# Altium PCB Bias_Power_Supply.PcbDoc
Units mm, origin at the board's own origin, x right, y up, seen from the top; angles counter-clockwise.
Board outline 100 x 60 mm, 4 copper layers (Top Layer, Layer 1, Layer 2, Bottom Layer), stack 0.603 mm thick; 70 components, 35 nets, 168 pads, 109 vias.
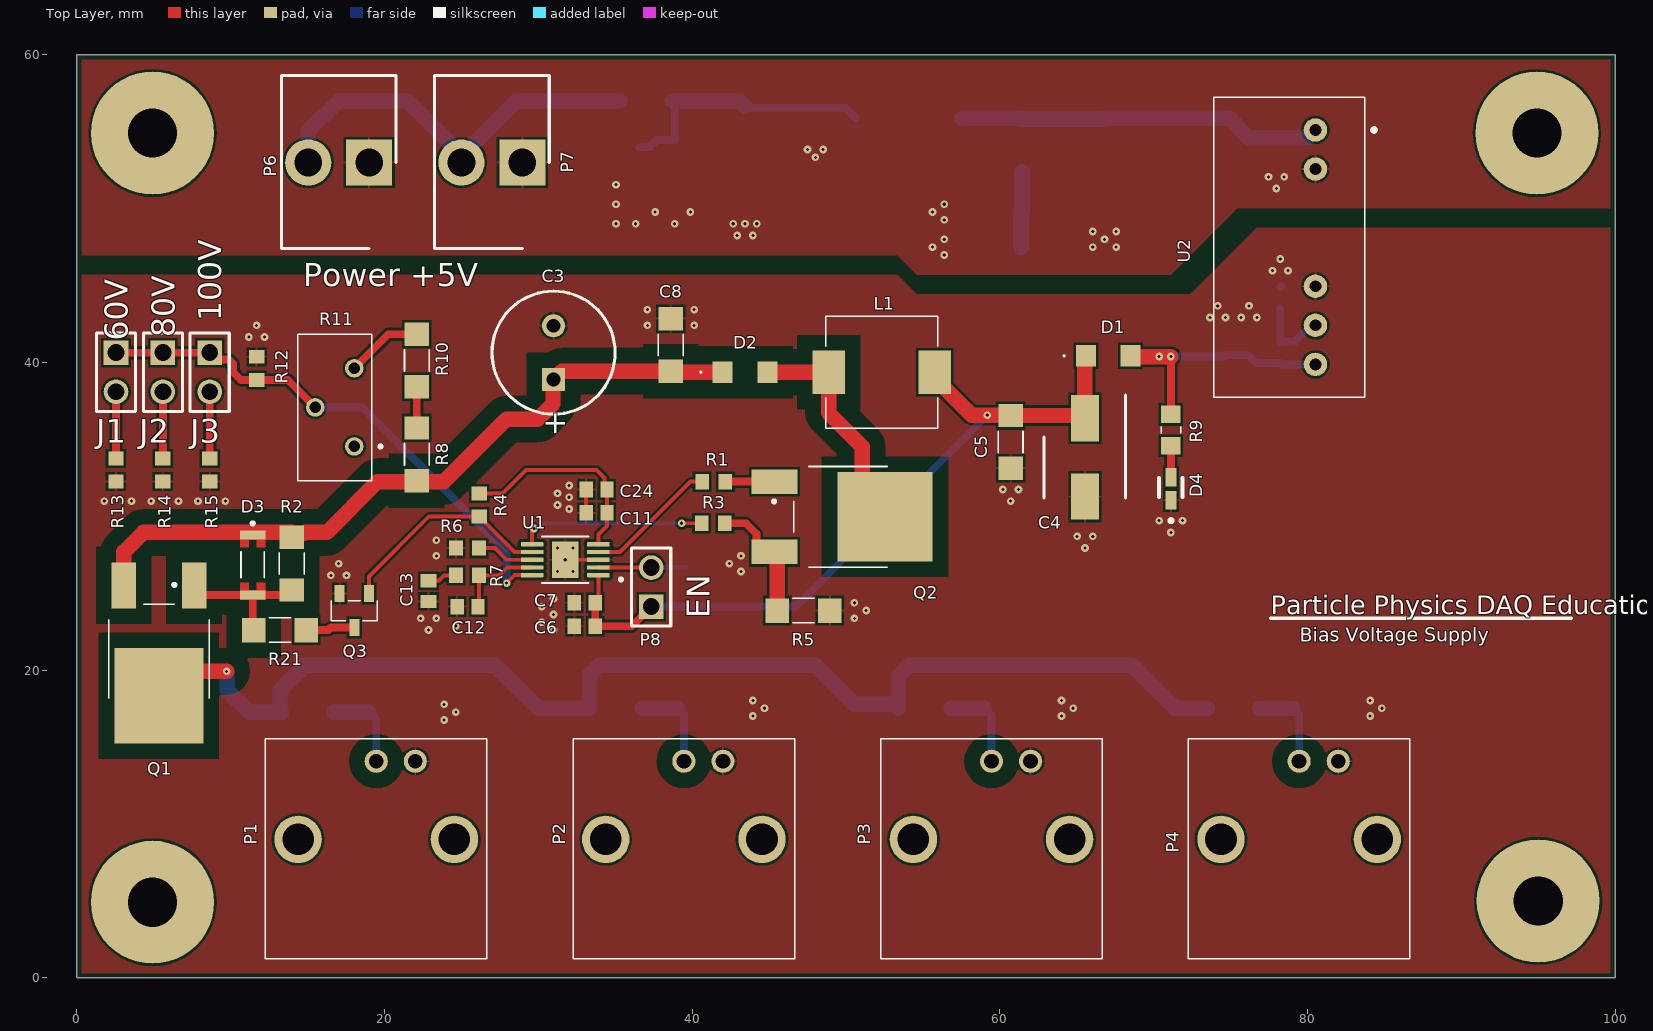
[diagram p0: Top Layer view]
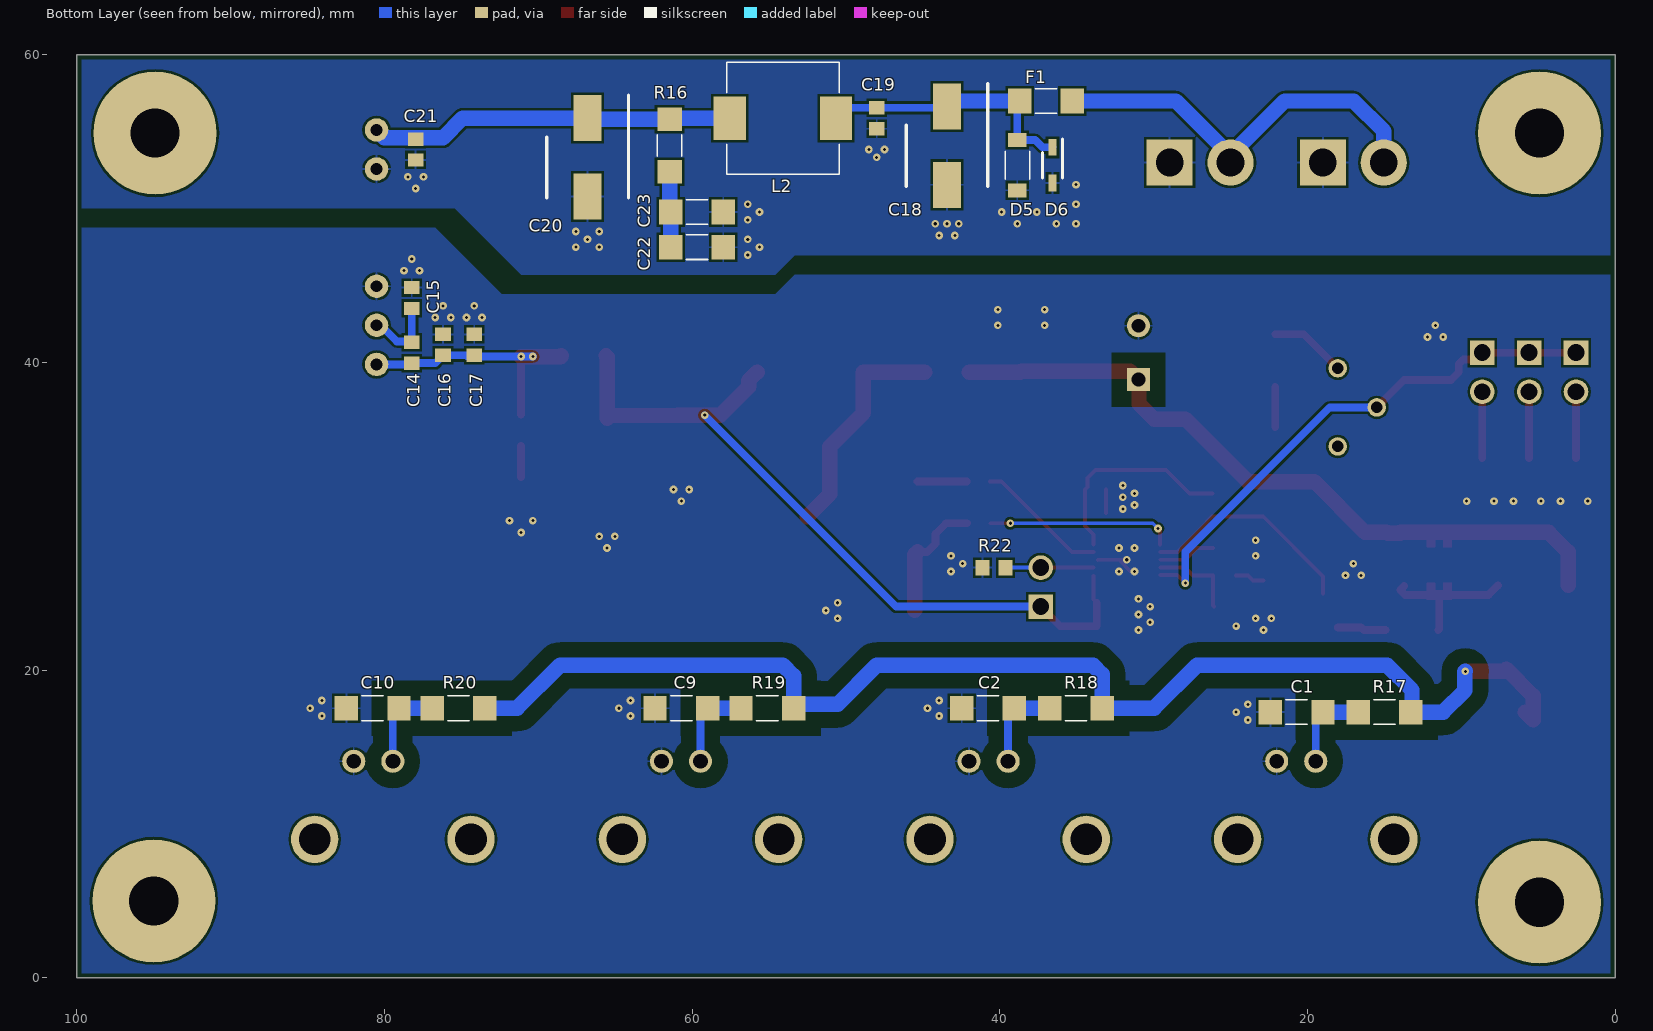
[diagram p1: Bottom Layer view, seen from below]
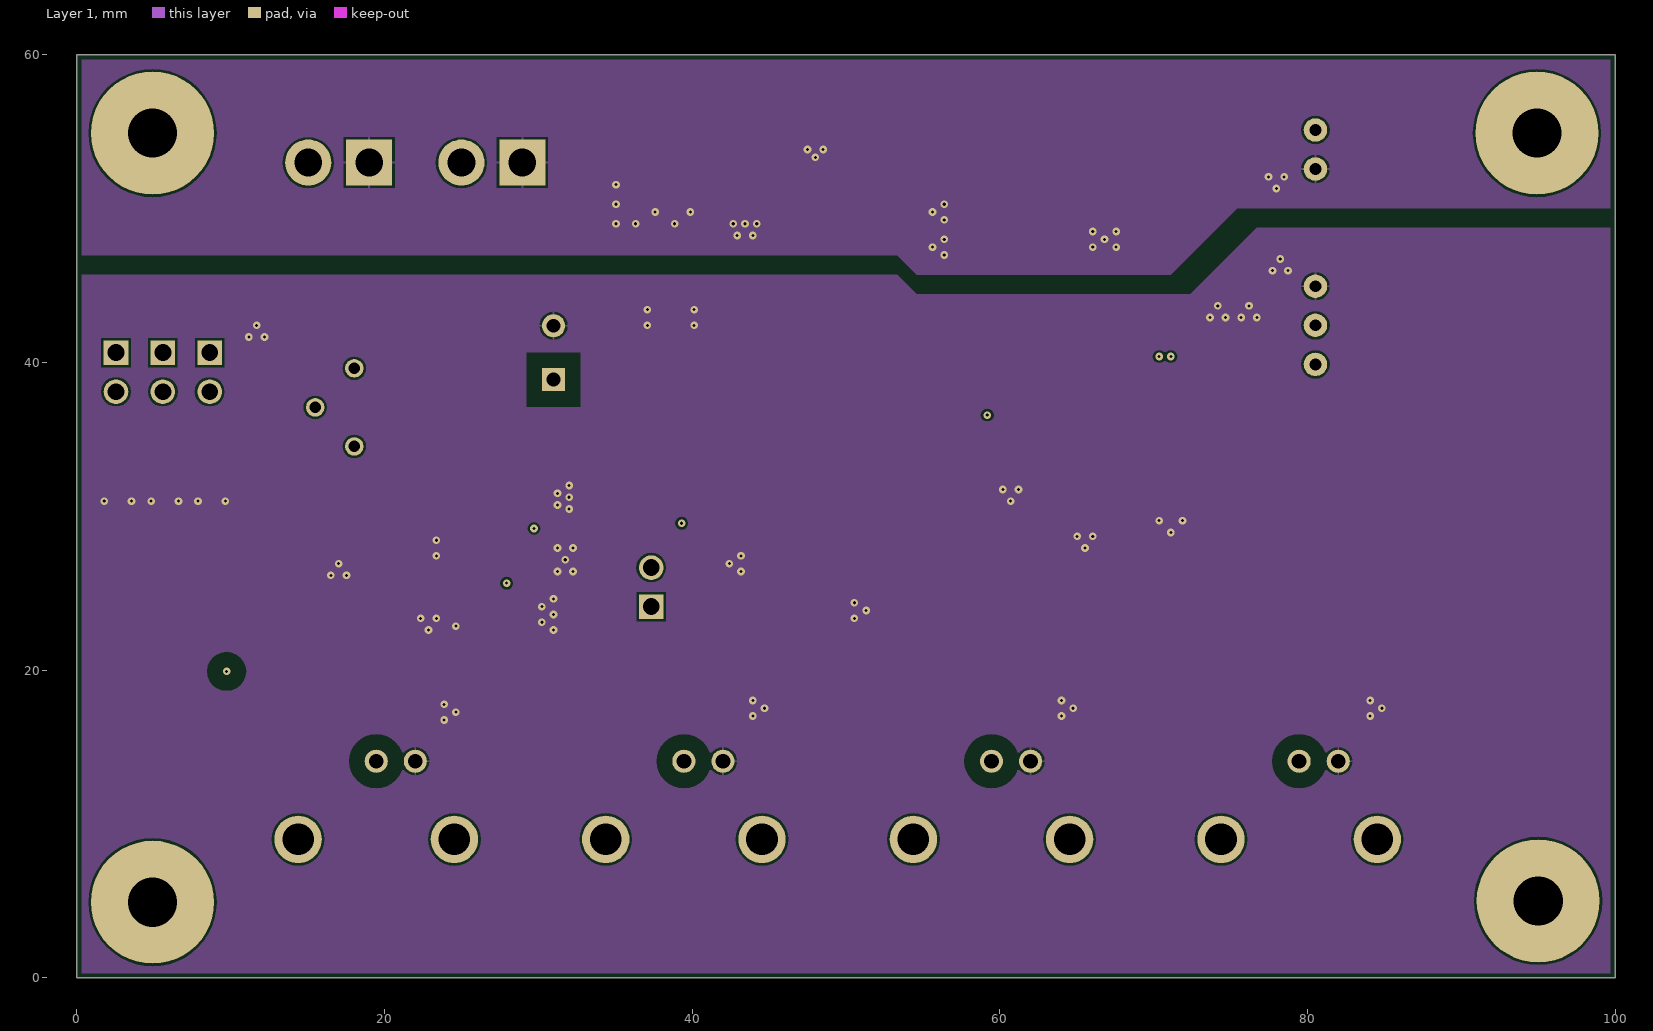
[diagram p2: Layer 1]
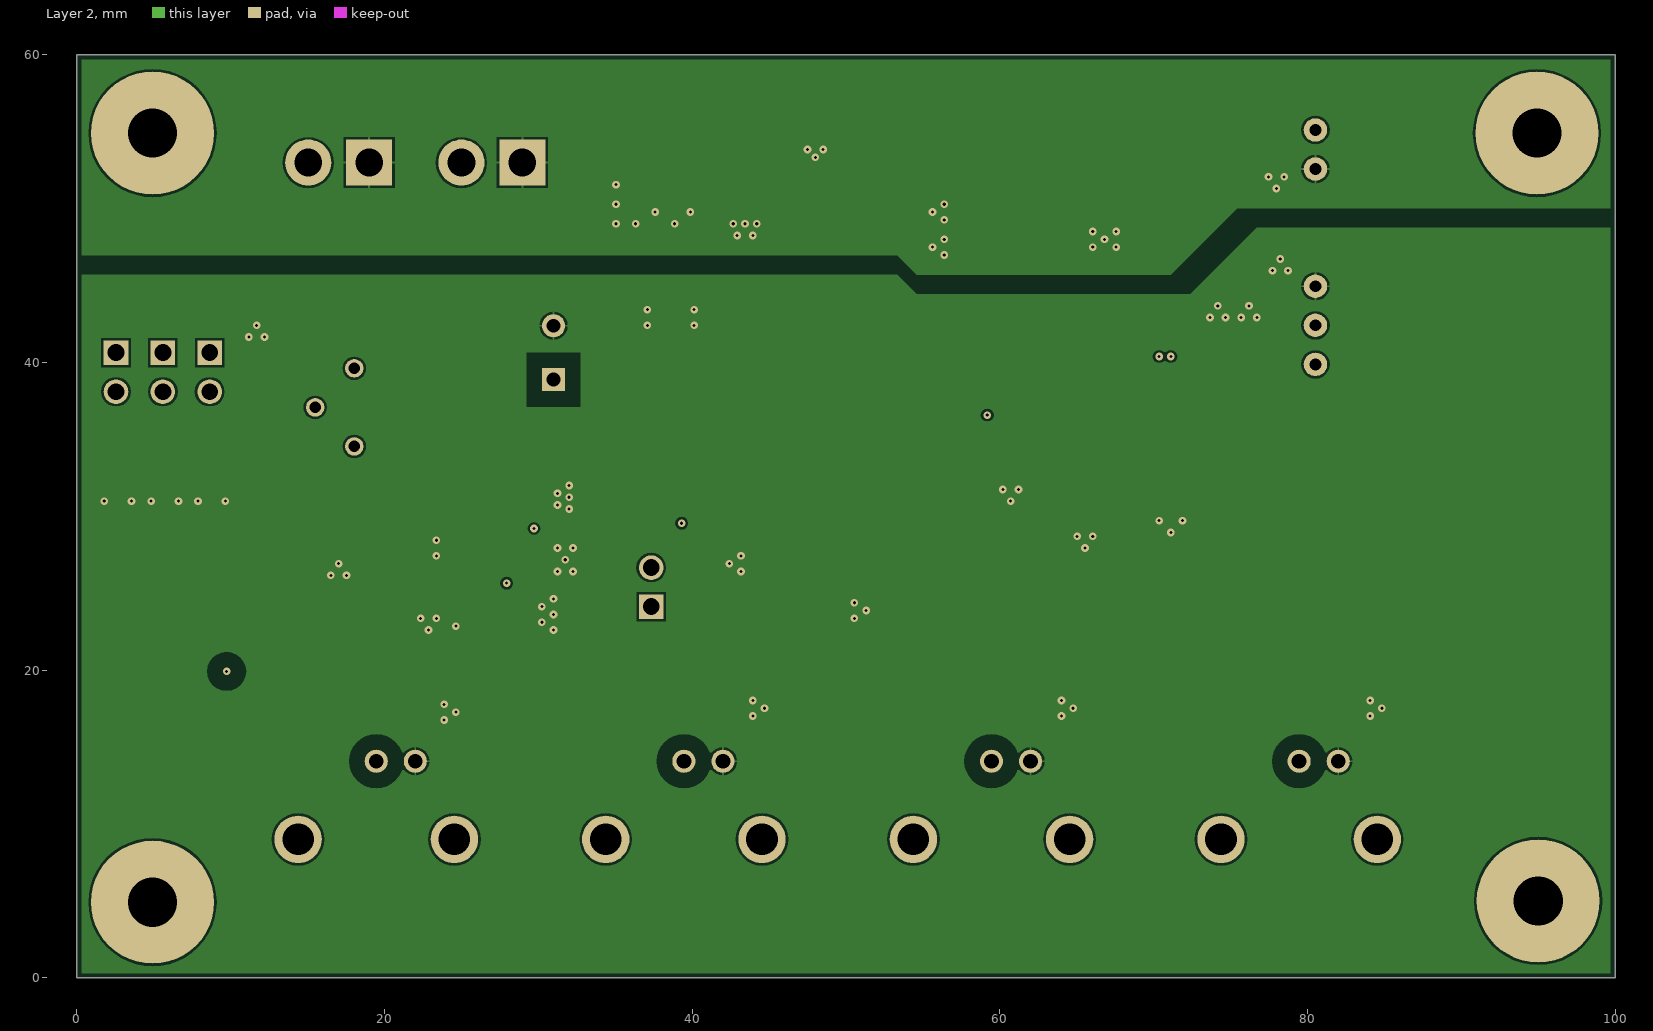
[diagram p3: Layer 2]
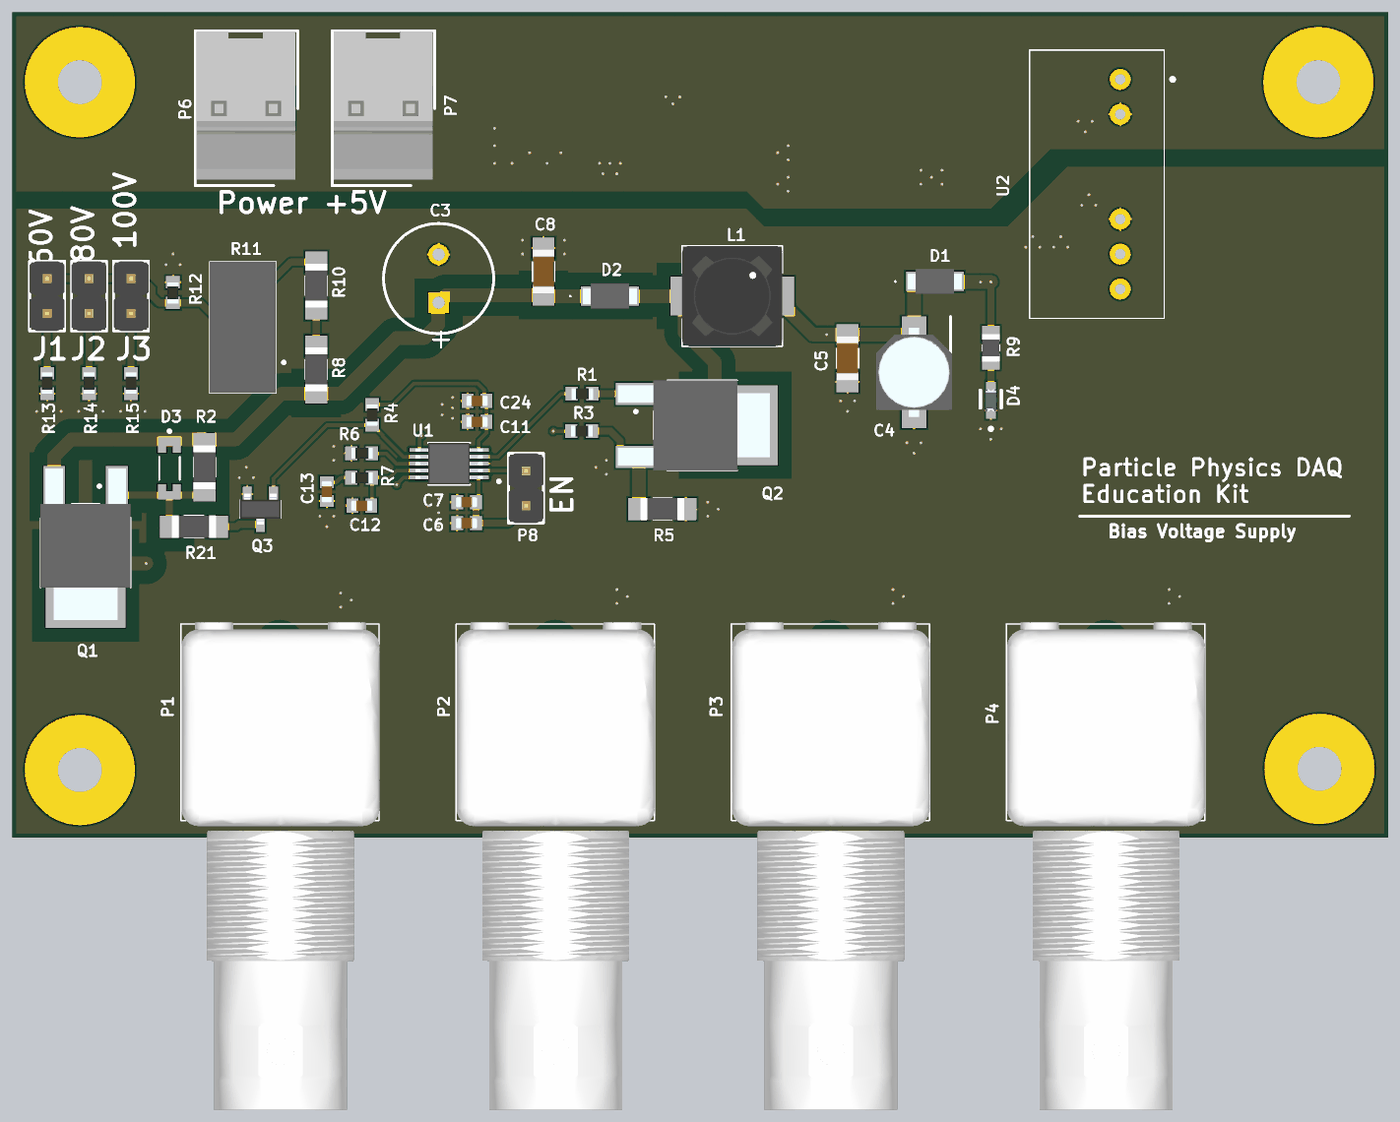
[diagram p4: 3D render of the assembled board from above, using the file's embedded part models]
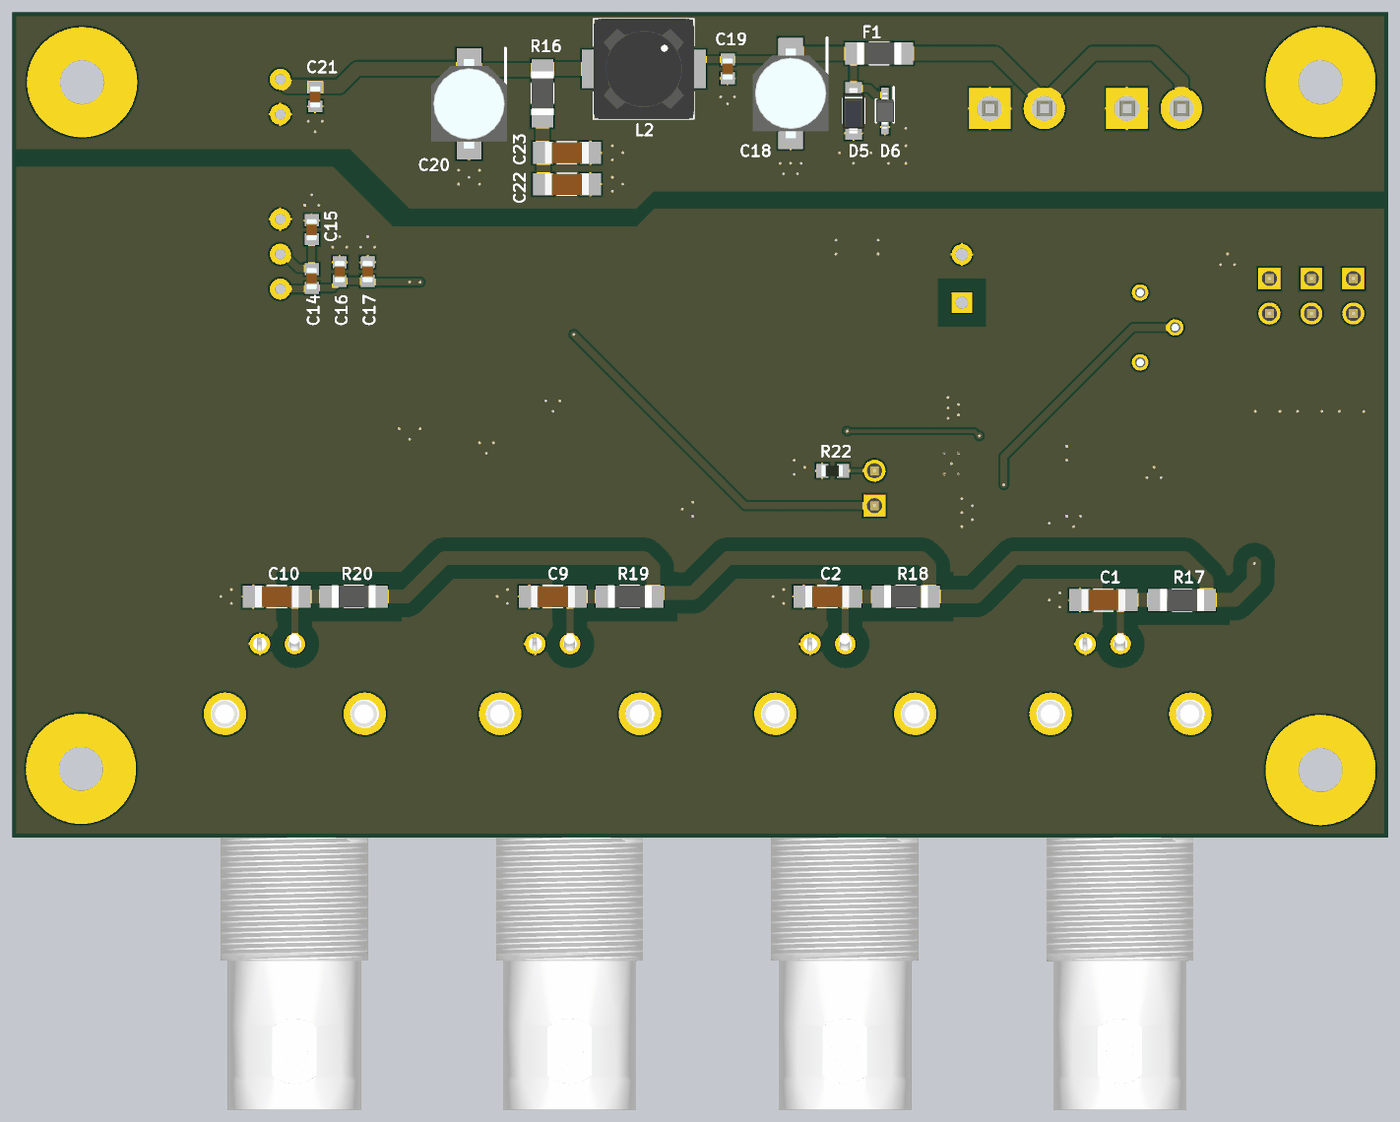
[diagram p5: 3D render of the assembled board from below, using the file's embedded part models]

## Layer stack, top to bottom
Top Solder: solder mask 0.0102, Solder Resist, Dk 3.5
Top Layer: signal copper 0.0356
Dielectric 2: prepreg 0.0711, PP-006, Dk 4.1
Layer 1: signal copper 0.035
Dielectric 1: core 0.32, FR-4, Dk 4.8
Layer 2: signal copper 0.035
Dielectric 3: prepreg 0.0711, PP-006, Dk 4.1
Bottom Layer: signal copper 0.0356
Bottom Solder: solder mask 0.0102, Solder Resist, Dk 3.5

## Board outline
0,0 0,60 100,60 100,0

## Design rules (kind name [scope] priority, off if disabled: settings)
AcuteAngle [All] p1: minimum=6.00000000000000E+0001 checktracksonly=FALSE
BoardOutlineClearance [All] p1: gap=0.3 ignorepadtopadclearanceinfootprint=FALSE
Clearance "Clearance - Controller" [HasFootprint('SOP50P490X110-11N')] p1: gap=0.2 ignorepadtopadclearanceinfootprint=FALSE
Clearance Clearance_HV [InNetClass('HV')] p2: gap=1 ignorepadtopadclearanceinfootprint=FALSE
Clearance "Clearance main" [All] p3: gap=0.15 ignorepadtopadclearanceinfootprint=FALSE
HoleSize [All] p1: absolutevalues=TRUE maxlimit=5 minlimit=0.2 maxpercent=80.000 minpercent=20.000
MinimumSolderMaskSliver [All] p1: minsoldermaskwidth=0.08
PolygonConnect [All] p1: thpad.connectstyle=Relief thpad.reliefconductorwidth=0.15 thpad.reliefentries=4 thpad.polygonreliefangle="90 Angle" thpad.airgapwidth=0.15 smdpad.connectstyle=Relief smdpad.reliefconductorwidth=0.15 smdpad.reliefentries=4 smdpad.polygonreliefangle="90 Angle" smdpad.airgapwidth=0.15 via.connectstyle=Direct via.reliefconductorwidth=0.254 via.reliefentries=4 via.polygonreliefangle="90 Angle" via.airgapwidth=0.254
RoutingVias [All] p1: holewidth=0.7 width=1.27 viastyle="Through Hole" minholewidth=0.7 minwidth=1.27 maxholewidth=0.7 maxwidth=1.27
SilkToSilkClearance [All] p1: silktosilkclearance=0.1
SilkToSolderMaskClearance [IsPad] p1: minsilkscreentomaskgap=0.1 clearancetoexposedcopper=TRUE
SolderMaskExpansion [All] p1: expansion=0.07
Width [All] p1: maxlimit=1.016 minlimit=0.254 preferedwidth=0.508
26 further rules are at their usual default settings.

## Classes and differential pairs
net class HV: HV_out NetC1_2 NetC2_2 NetC3_1 NetC9_2 NetC10_2 NetD2_1 NetD3_1

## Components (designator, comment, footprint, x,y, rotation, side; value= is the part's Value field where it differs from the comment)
C1 "100n" SMD_CAPACITOR_1206 20.701,17.272 r180 bottom
C2 "100n" SMD_CAPACITOR_1206 40.767,17.526 r180 bottom
C3 "10u" CAPPR3.5-8x11.5 30.988,40.64 r90 top
C4 "10u" SMD_CAP_POL_D5.0mm 65.532,33.83 r270 top
C5 "10u" SMD_CAPACITOR_1206 60.706,34.846 r90 top
C6 "1u" SMD_CAPACITOR_0603 33.02,22.86 r0 top
C7 "100n" SMD_CAPACITOR_0603 33.02,24.384 r0 top
C8 "100n" SMD_CAPACITOR_1206 38.608,41.148 r270 top
C9 "100n" SMD_CAPACITOR_1206 60.706,17.526 r180 bottom
C10 "100n" SMD_CAPACITOR_1206 80.772,17.526 r180 bottom
C11 "100n" SMD_CAPACITOR_0603 33.782,30.226 r0 top
C12 "D.N.P." SMD_CAPACITOR_0603 25.4,24.13 r0 top
C13 "1n" SMD_CAPACITOR_0603 22.86,25.146 r90 top
C14 "100n" SMD_CAPACITOR_0603 78.232,40.64 r270 bottom
C15 "100n" SMD_CAPACITOR_0603 78.232,44.196 r270 bottom
C16 "100n" SMD_CAPACITOR_0603 76.2,41.148 r270 bottom
C17 "1u" SMD_CAPACITOR_0603 74.168,41.148 r270 bottom
C18 "10u" SMD_CAP_POL_D5.0mm 43.434,54.102 r270 bottom
C19 "100n" SMD_CAPACITOR_0603 48.006,55.88 r90 bottom
C20 "10u" SMD_CAP_POL_D5.0mm 66.802,53.34 r270 bottom
C21 "100n" SMD_CAPACITOR_0603 77.978,53.848 r90 bottom
C22 "10u" SMD_CAPACITOR_1206 59.69,47.498 r0 bottom
C23 "10u" SMD_CAPACITOR_1206 59.69,49.784 r0 bottom
C24 "2u2" SMD_CAPACITOR_0603 33.782,31.75 r0 top
D1 "V1F22HM3/H" SMD_DO-219 67.056,40.434 r180 top
D2 "V1F22HM3/H" SMD_DO-219 43.434,39.37 r180 top
D3 "BZM55C20" SMD_DIO-MINIMELF 11.43,26.842 r270 top
D4 "GREEN" SMD_LED_0603 71.12,31.798 r90 top
D5 "1N4148W" SMD_SOD-123 38.862,52.832 r90 bottom
D6 "SD05T1G" SMD_SOD-323 36.576,52.832 r270 bottom
F1 "Fuse" SMD_RESISTOR_1206 37,57 r0 bottom
J1 "Header_2pin_1row" 61300211121 2.54,40.64 r270 top
J2 "Header_2pin_1row" 61300211121 5.588,40.64 r270 top
J3 "Header_2pin_1row" 61300211121 8.636,40.64 r270 top
L1 "100u" SMD_INDUCTOR_7.3MM 52.324,39.37 r180 top
L2 "220uH" SMD_INDUCTOR_7.3MM 54.102,55.88 r0 bottom
P1 "BNC" BNC_0315637 22,14.08 r180 top
P2 "BNC" BNC_0315637 42,14.08 r180 top
P3 "BNC" BNC_0315637 62,14.08 r180 top
P4 "BNC" BNC_0315637 82,14.08 r180 top
P6 "09-65-2028" SHDR2W165P0X396_1X2_716X1062X1425P 19,53 r180 top
P7 "09-65-2028" SHDR2W165P0X396_1X2_716X1062X1425P 28.96,53 r180 top
P8 "Header_2pin_1row" 61300211121 37.338,24.13 r90 top
Q1 "FQD5P20TM" SMD_DPAK 5.334,21.844 r90 top
Q2 "FQD5N20LTM" SMD_DPAK 49.022,29.972 r180 top
Q3 "BSS131H6327XTSA1" SMD_SOT-23 18.034,23.876 r180 top
R1 "0" SMD_RES_0603 41.402,32.258 r0 top
R2 "100k" SMD_RESISTOR_1206 13.97,26.924 r90 top
R3 "470" SMD_RES_0603 41.369,29.551 r0 top
R4 "10k" SMD_RES_0603 26.162,30.734 r270 top
R5 "0.56" SMD_RESISTOR_1206 47.244,23.876 r180 top
R6 "12k" SMD_RES_0603 25.4,27.94 r0 top
R7 "4k7" SMD_RES_0603 25.4,26.162 r0 top
R8 "47k" SMD_RESISTOR_1206 22.098,34.036 r90 top
R9 "1k2" SMD_RESISTOR_0805 71.12,35.608 r270 top
R10 "10k" SMD_RESISTOR_1206 22.098,40.132 r90 top
R11 "20k" THT_TRIM_3296Y1502LF 18.034,34.544 r0 top
R12 "2k6" SMD_RES_0603 11.684,39.624 r270 top
R13 "4k7" SMD_RES_0603 2.54,33.02 r90 top
R14 "2k4" SMD_RES_0603 5.588,33.02 r90 top
R15 "1k6" SMD_RES_0603 8.636,33.02 r90 top
R16 "6R8" SMD_RESISTOR_1206 61.468,54.102 r90 bottom
R17 "10k" SMD_RESISTOR_1206 14.986,17.272 r180 bottom
R18 "10k" SMD_RESISTOR_1206 35.052,17.526 r180 bottom
R19 "10k" SMD_RESISTOR_1206 55.118,17.526 r180 bottom
R20 "10k" SMD_RESISTOR_1206 75.184,17.526 r180 bottom
R21 "10k" SMD_RESISTOR_1206 13.208,22.606 r180 top
R22 "10k" SMD_RES_0603 40.386,26.67 r0 bottom
U1 "MAX16992AUBA/V+" SOP50P490X110-11N 31.75,27.178 r180 top
U2 "AM2DM - DH" AM2DM_dual_3 80.518,55.118 r270 top

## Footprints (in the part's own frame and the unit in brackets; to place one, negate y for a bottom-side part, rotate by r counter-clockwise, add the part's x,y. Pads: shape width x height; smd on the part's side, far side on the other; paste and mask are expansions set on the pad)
61300211121 [mm] "2 pins, 1 row, straight, gold plating"
  rect 1.6x1.6 hole 1.1: 1(0,0)
  round 1.6 hole 1.1: 2(2.54,0)
  silkscreen extent -1.27,-1.27 3.81,1.27, body extent -1.27,-1.27 3.81,1.27, height 8.54
AM2DM_dual_3 [mil]
  round 60 hole 30: 1(0,0) 2(100,0) 5(400,0) 6(500,0) 7(600,0)
  silkscreen extent -84,-260 684,155, body extent -84,-260 684,126, height 492
BNC_0315637 [mm]
  round 1.501 hole 0.965: 1(0,0) 2(2.54,0)
  round 3.085 hole 2.057: MH1(-2.54,5.08) MH2(7.62,5.08)
  silkscreen extent -4.66,-1.45 9.74,12.83, body extent -4.7,-1.56 9.7,33.85, height 12.98
CAPPR3.5-8x11.5 [mm] "Capacitor, Electrolytic, Radial; Body 8 x 11.5 mm (Dia.xH typ); Pin Spacing 3.5 mm (typ)"
  rect 1.5x1.5 hole 0.9: 1(-1.75,0)
  round 1.5 hole 0.9: 2(1.75,0)
  silkscreen extent -4,-4 4,4
SHDR2W165P0X396_1X2_716X1062X1425P [mm]
  rect 3x3 hole 1.8: 1(0,0)
  round 3 hole 1.8: 2(3.96,0)
  silkscreen extent -1.75,-5.65 5.71,5.6, body extent -1.58,-5.6 5.58,5.15, height 13.85
SMD_CAP_POL_D5.0mm [mm]
  rect 3x1.8 smd: 1(-2.55,0) 2(2.55,0)
  silkscreen extent -4.05,-2.65 2.65,2.65, body extent -3.25,-2.75 3.25,2.75, height 6.1
SMD_CAPACITOR_0603 [mm]
  rect 0.87x1.02 smd: 1(-0.68,0) 2(0.68,0)
  body extent -0.8,-0.4 0.8,0.4, height 1
SMD_CAPACITOR_1206 [mm]
  rect 1.52x1.6 smd: 1(-1.71,0) 2(1.71,0)
  silkscreen extent -0.7,-0.8 0.7,0.8, body extent -1.6,-0.8 1.6,0.8, height 1.58
SMD_DIO-MINIMELF [mm]
  rect 0.6x1.65 smd: A(1.95,0) C(-1.95,0)
  Top Layer region: -1.15,0.25 -1.65,0.25 -1.65,-0.25 -1.15,-0.25 -1.15,-0.825 -2.24,-0.825 -2.24,0.825 -1.15,0.825
  Top Layer region: 2.25,-0.825 1.15,-0.825 1.15,-0.25 1.65,-0.25 1.65,0.25 1.15,0.25 1.15,0.825 2.25,0.825
  silkscreen extent -2.8,-0.75 0.83,0.75
SMD_DO-219 [mm]
  rect 1.3x1.4 smd: 1(-1.45,0) 2(1.45,0)
  silkscreen extent 2.82,-0.05 2.92,0.05, body extent -1.97,-0.9 1.97,0.9, height 1.18
SMD_DPAK [mm]
  rect 3x1.6 smd: 1(3.667,-2.285) 3(3.667,2.285)
  rect 6.2x5.8 smd: 4(-3.512,0)
  silkscreen extent -3.67,-3.27 3.8,3.27, body extent -6.03,-3.27 5.01,3.27, height 2.38
SMD_INDUCTOR_7.3MM [mm]
  rect 2.1x2.8 smd: 1(-3.45,0) 2(3.45,0)
  silkscreen extent -3.65,-3.65 3.65,3.65, body extent -3.65,-3.65 3.65,3.65, height 4
SMD_LED_0603 [mm]
  rect 1.2x0.7 smd: 1(0.75,0) 2(-0.75,0)
  body extent -0.8,-0.4 0.8,0.4, height 0.36
SMD_RES_0603 [mm]
  rect 0.9x1 smd: 1(-0.75,0) 2(0.75,0)
  body extent -0.75,-0.4 0.8,0.4, height 0.55
SMD_RESISTOR_0805 [mm]
  rect 1.14x1.27 smd: 1(-1.015,0) 2(1.015,0)
  silkscreen extent -0.2,-0.64 0.2,0.64, body extent -1,-0.64 1,0.64, height 0.61
SMD_RESISTOR_1206 [mm]
  rect 1.52x1.6 smd: 1(-1.71,0) 2(1.71,0)
  silkscreen extent -0.7,-0.8 0.7,0.8, body extent -1.6,-0.81 1.6,0.81, height 0.61
SMD_SOD-123 [mm]
  rect 0.91x1.2 smd: 1(-1.635,0) 2(1.635,0)
  silkscreen extent -0.9,-0.8 0.9,0.8, body extent -1.65,-0.8 1.65,0.8, height 1.2
SMD_SOD-323 [mm]
  rect 1.088x0.55 smd: 1(1.158,0) 2(-1.158,0)
  silkscreen extent -1.7,-0.64 0.82,0.64, body extent -1.29,-0.64 1.29,0.64, height 1.17
SMD_SOT-23 [mm]
  rect 0.65x1.1 smd: 1(-0.95,-1.1) 2(0.95,-1.1) 3(0,1.1)
  silkscreen extent -1.5,-0.65 1.5,0.65, body extent -1.5,-1.13 1.5,1.13, height 1.22
SOP50P490X110-11N [mm]
  rrect25% 1.47x0.28 smd: 1(-2.15,1) 2(-2.15,0.5) 3(-2.15,0) 4(-2.15,-0.5) 5(-2.15,-1) 6(2.15,-1) 7(2.15,-0.5) 8(2.15,0) 9(2.15,0.5) 10(2.15,1)
  rect 1.727x2.362 smd paste-2: 11(0,0)
  silkscreen extent -3.72,-1.53 1.53,1.53, body extent -2.45,-1.5 2.45,1.5, height 1.1
THT_TRIM_3296Y1502LF [mm]
  round 1.2 hole 0.75: 1(0,0) 2(-2.54,2.54) 3(0,5.08)
  silkscreen extent -3.68,-2.22 1.8,7.3, body extent -3.68,-2.22 1.14,7.31, height 10.13

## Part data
C1 C2 C5 C6 C7 C8 C9 C10 C11 C12 C13 C14 C15 C16 C17 C19 C21 C22 C23 C24: library part Capacitor
C3 C4 C18 C20: library part Capacitor_pol
D1 D2: library part Schottky_Diode
D3: library part Zener_Diode
D4: library part LED
D5: library part Diode
D6: library part TVS_Diode_unidirect
J1 J2 J3 P8: Manufacturer="Wurth Electronics", Package="2-pin, 2.54 mm", Part Number=61300211121
L1 L2: library part Inductor
P6 P7: "Connector", Manufacturer_Name=Molex, Mouser Part Number=538-09-65-2028, RS Part Number=6705237P
Q1: library part Transistor_P-mosfet
Q2 Q3: library part Transistor_N-Mosfet
R1 R2 R3 R4 R5 R6 R7 R8 R9 R10 R12 R13 R14 R15 R16 R17 R18 R19 R20 R21 R22: library part Resistor
R11: library part Resistor_trim

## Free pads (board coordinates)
  round 8 hole 3.2: ""(4.92,4.915) ""(4.92,54.915) ""(94.92,54.915) ""(95,5)

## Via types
v1: diameter 0.5, hole 0.2, Top Layer to Bottom Layer, 109 vias

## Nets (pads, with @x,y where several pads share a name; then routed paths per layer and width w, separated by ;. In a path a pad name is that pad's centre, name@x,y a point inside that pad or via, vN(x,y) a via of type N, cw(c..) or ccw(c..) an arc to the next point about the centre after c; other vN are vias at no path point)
EN: P8.2 R22.1 U1.2 | length 5.9
  Top Layer w0.254: U1.2 36.068,26.678 ; 36.217,26.678 36.068,26.678 ; P8.2 36.217,26.67 36.076,26.67 36.068,26.678
  Bottom Layer w0.254: P8.2 R22.1@39.624,26.67
FB: J1.1 J2.1 J3.1 R11.2 R12.2 U1.10 | length 34.2
  Top Layer w0.254: v1(27.94,25.654) 28.464,26.178 U1.10@29.55,26.178
  Top Layer w0.508: J1.1@3.298,40.64 J3.1 9.071,40.205 9.862,40.205 10.16,39.907 10.16,39.37 10.656,38.874 R12.2 13.704,38.874 R11.2
  Bottom Layer w0.508: R11.2 18.542,37.084 27.94,27.686 v1(27.94,25.654)
GND: C1.1 C2.1 C3.2 C4.2 C5.1 C6.1 C7.1 C8.1 C9.1 C10.1 C11.1 C12.1 C13.1 C15.1 C16.1 C17.1 C24.1 D4.2 P1.1 P2.1 P3.1 P4.1 Q3.2 R5.1 R6.1 R12.1 R13.1 R14.1 R15.1 R22.2 U1.3 U1.11 U2.5 | length 4.6
  Top Layer w0.254: U1.11@31.496,26.416 U1.11@32.258,27.178 ; v1(31.75,27.178) U1.11@32.258,27.178 ; C11.1 C24.1 ; U1.3@33.632,27.163 33.617,27.178 U1.11@32.258,27.178
  Bottom Layer w0.508: C15.1 C15.1@78.314,44.958
  other v1: 23.876,16.764 43.942,17.018 64.008,17.018 84.074,17.018 24.638,17.272 44.704,17.526 64.77,17.526 84.836,17.526 23.876,17.78 43.942,18.034 64.008,18.034 84.074,18.034 22.86,22.606 30.988,22.606 24.638,22.86 30.226,23.114 22.352,23.368 23.368,23.368 50.546,23.368 30.988,23.622 51.308,23.876 30.226,24.13 50.546,24.384 30.988,24.638 16.51,26.162 17.526,26.162 31.242,26.416 32.258,26.416 43.18,26.416 17.018,26.924 42.418,26.924 23.368,27.432 43.18,27.432 31.242,27.94 32.258,27.94 65.532,27.94 23.368,28.448 65.024,28.702 66.04,28.702 71.12,28.956 70.358,29.718 71.882,29.718 32.004,30.48 31.242,30.734 1.778,30.988 3.556,30.988 4.826,30.988 6.604,30.988 7.874,30.988 9.652,30.988 60.706,30.988 32.004,31.242 31.242,31.496 60.198,31.75 61.214,31.75 32.004,32.004 11.176,41.656 12.192,41.656 11.684,42.418 37.084,42.418 40.132,42.418 73.66,42.926 74.676,42.926 75.692,42.926 76.708,42.926 37.084,43.434 40.132,43.434 74.168,43.688 76.2,43.688 77.724,45.974 78.74,45.974 78.232,46.736
HV_out: Q1.4 R17.2 R18.2 R19.2 R20.2 | length 83.5
  Top Layer w1: Q1.4@5.842,17.272 5.334,16.764 Q1.4 7.068,20.066 7.211,19.923 v1(9.735,19.923)
  Bottom Layer w1: v1(9.735,19.923) 9.768,19.89 9.768,18.68 11.176,17.272 R17.2 13.208,17.34 13.208,18.709 14.819,20.32 27.178,20.32 29.972,17.526 R18.2 33.342,19.725 33.937,20.32 48.006,20.32 50.546,17.78 53.156,17.78 R19.2 53.408,19.626 54.102,20.32 68.58,20.32 71.374,17.526 R20.2
IGND: C18.2 C19.1 C20.2 C21.1 C22.1 C23.1 D5.1 D6.1 P6.1 P7.1 U2.2
  other v1: 56.388,46.99 55.626,47.498 66.04,47.498 67.564,47.498 56.388,48.006 66.802,48.006 42.926,48.26 43.942,48.26 66.04,48.514 67.564,48.514 35.052,49.022 36.322,49.022 38.862,49.022 42.672,49.022 43.434,49.022 44.196,49.022 56.388,49.276 37.592,49.784 39.878,49.784 55.626,49.784 35.052,50.292 56.388,50.292 77.978,51.308 35.052,51.562 77.47,52.07 78.486,52.07 48.006,53.34 47.498,53.848 48.514,53.848
NetC1_2: C1.2 P1.2 R17.1 | length 5.7
  Bottom Layer w0.508: C1.2 19.46,16.803 P1.2
  Bottom Layer w1: R17.1 C1.2
NetC2_2: C2.2 P2.2 R18.1 | length 5.9
  Bottom Layer w0.508: C2.2 39.46,17.123 P2.2
  Bottom Layer w1: R18.1 C2.2
NetC3_1: C3.1 C8.2 D2.2 D3.C Q1.3 R2.2 R8.1 | length 46.9
  Top Layer w1: Q1.3 3.049,27.687 4.318,28.956 11.43,28.956 R2.2@13.97,28.956 ; R2.2@13.97,28.894 14.794,28.894 14.856,28.956 16.256,28.956 19.558,32.258 22.098,32.258 23.865,32.258 27.929,36.322 29.972,36.322 30.952,37.302 30.952,38.854 31.536,39.438 C8.2 38.676,39.37 D2.2
NetC9_2: C9.2 P3.2 R19.1 | length 5.8
  Bottom Layer w0.508: C9.2 59.46,17.062 P3.2
  Bottom Layer w1: R19.1 C9.2
NetC10_2: C10.2 P4.2 R20.1 | length 5.8
  Bottom Layer w0.508: C10.2 79.46,17.128 P4.2
  Bottom Layer w1: R20.1 C10.2
NetC11_2: C11.2 C24.2 R4.1 U1.5 | length 13.6
  Top Layer w0.254: R4.1 27.674,31.484 29.21,33.02 33.782,33.02 34.31,32.492 34.31,31.902 C24.2 C11.2 34.462,29.382 33.9,28.82 U1.5
NetC12_2: C12.2 R7.2 U1.9 | length 5.7
  Top Layer w0.254: C12.2 26.15,24.2 R7.2 27.432,26.162 27.948,26.678 U1.9@29.55,26.678
NetC13_2: C13.2 R7.1 | length 1.9
  Top Layer w0.254: C13.2 23.54,25.826 23.876,26.162 R7.1
NetC14_1: C14.1 C15.2 U2.6 | length 4.9
  Bottom Layer w0.508: C15.2 78.232,41.501 C14.1 78.287,41.375 79.2,41.375 80.243,42.418 U2.6
NetC18_1: C18.1 C19.2 D5.2 D6.2 F1.2 L2.1 | length 17.5
  Bottom Layer w0.508: D6.2 37.226,53.99 37.703,54.467 D5.2 38.862,56.848 F1.2 ; C18.1 43.526,56.56 C19.2 49.972,56.56 L2.1
  Bottom Layer w1: F1.2 43.086,57 C18.1
NetC20_1: C20.1 C21.2 L2.2 R16.2 U2.1 | length 23.8
  Bottom Layer w1: L2.2 61.4,55.88 R16.2 66.724,55.812 C20.1 74.92,55.89 76.2,54.61 80.01,54.61 U2.1
NetC22_2: C22.2 C23.2 R16.1 | length 4.9
  Bottom Layer w1: C22.2 C23.2 61.468,49.852 R16.1
NetD2_1: D2.1 L1.2 Q2.4 | length 14.9
  Top Layer w1: D2.1 L1.2 48.874,36.724 51.054,34.544 51.054,31.452 Q2.4
NetD3_1: D3.A Q1.1 R2.1 R21.2 | length 9.4
  Top Layer w0.508: Q1.1 8.238,24.892 D3.A ; R21.2 11.43,22.674 D3.A ; R2.1@13.71,25.474 R2.1 13.648,24.892 D3.A
NetD4_1: D4.1 R9.2 | length 2
  Top Layer w0.508: D4.1 R9.2
NetF1_1: F1.1 P6.2 P7.2 | length 27
  Bottom Layer w1: P6.2 15.04,55.04 17,57 21.486,57 25,53.486 P7.2 25,53.448 28.552,57 F1.1
NetJ1_2: J1.2 R13.2 | length 4.3
  Top Layer w0.508: R13.2@2.54,33.782 J1.2
NetJ2_2: J2.2 R14.2 | length 4.3
  Top Layer w0.508: R14.2@5.588,33.782 J2.2
NetJ3_2: J3.2 R15.2 | length 4.3
  Top Layer w0.508: R15.2@8.636,33.782 J3.2
NetQ2_G: Q2.1 R1.2 | length 3.2
  Top Layer w0.508: R1.2 45.354,32.258 Q2.1
NetQ2_S: Q2.3 R3.2 R5.2 | length 8.3
  Top Layer w0.508: R3.2 43.491,29.551 44.174,28.868 44.174,28.233 44.72,27.687 Q2.3
  Top Layer w1: Q2.3 45.534,27.508 R5.2
NetQ3_D: Q3.3 R21.1 | length 3.2
  Top Layer w0.508: R21.1 16.34,22.606 16.51,22.776 Q3.3
NetR1_1: R1.1 U1.4 | length 8.6
  Top Layer w0.254: U1.4 35.298,27.678 39.878,32.258 R1.1
NetR3_1: R3.1 U1.6 | length 12.1
  Top Layer w0.254: U1.6 29.6,29.025 29.718,29.143 v1(29.718,29.21) ; v1(39.316,29.551) R3.1
  Bottom Layer w0.254: v1(29.718,29.21) 30.059,29.551 v1(39.316,29.551)
NetR6_2: R6.2 U1.8 | length 3.7
  Top Layer w0.254: R6.2 27.178,27.94 27.94,27.178 U1.8@29.55,27.178
NetR8_2: R8.2 R10.1 | length 2.6
  Top Layer w0.508: R8.2@22.098,35.814 R10.1
NetR10_2: R10.2 R11.3 | length 5
  Top Layer w0.508: R11.3 20.252,41.842 R10.2
PGOOD: Q3.1 R4.2 U1.7 | length 14.3
  Top Layer w0.254: Q3.1 18.984,26.096 22.872,29.984 26.212,29.984 26.535,29.661 26.535,29.611 26.924,29.222 26.924,29.21 28.456,27.678 U1.7@29.55,27.678
SUP: C4.1 C5.2 C6.2 C7.2 D1.2 L1.1 P8.1 U1.1 | length 50.1
  Top Layer w0.254: C7.2 33.9,24.584 U1.1@33.9,26.124
  Top Layer w0.508: C7.2 C6.2 36.068,22.86 P8.1 ; C5.2@60.686,36.576 C5.2
  Top Layer w1: L1.1 56.324,38.82 56.324,38.418 58.166,36.576 v1(59.182,36.576) 60.686,36.576 C5.2@60.96,36.576 ; C5.2 65.356,36.556 C4.1 65.532,40.36 D1.2
  Bottom Layer w0.508: P8.1 46.736,24.13 v1(59.182,36.576)
VCC: C14.2 C16.2 C17.2 D1.1 R9.1 U2.7 | length 17.1
  Top Layer w0.508: R9.1 v1(71.12,40.386)
  Top Layer w1: D1.1 68.554,40.386 v1(70.358,40.386) v1(71.12,40.386)
  Bottom Layer w0.508: v1(70.358,40.386) v1(71.12,40.386) 74.594,40.386 C17.2@74.676,40.468 ; C17.2@74.422,40.468 C17.2@74.676,40.468 ; U2.7 78.314,39.878 C14.2 76.708,39.96 C16.2 C17.2@74.676,40.468
pads on no net: P1.MH1 P1.MH2 P2.MH1 P2.MH2 P3.MH1 P3.MH2 P4.MH1 P4.MH2 R11.1

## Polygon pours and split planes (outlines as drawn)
IGND on Bottom Layer "Top Layer-No Net" (solid, remove dead copper, pour order 6): 0,46.99 53.34,46.99 54.61,45.72 71.12,45.72 75.438,50.038 100,50.038 100,60 0,60
GND on Bottom Layer "Top Layer-No Net" (solid, remove dead copper, pour order 8): 0,45.72 53.34,45.72 54.61,44.45 72.39,44.45 76.708,48.768 100,48.768 100,0 0,0
IGND on Top Layer "Top Layer-No Net" (solid, remove dead copper, pour order 4): 71.12,45.72 75.438,50.038 100,50.038 100,60 0,60 0,46.99 53.34,46.99 54.61,45.72
GND on Top Layer "Top Layer-No Net" (solid, remove dead copper, pour order 12): 0,45.72 53.34,45.72 54.61,44.45 72.39,44.45 76.708,48.768 100,48.768 100,0 0,0
IGND on Layer 1 "Top Layer-No Net" (solid, remove dead copper, pour order 15): 71.12,45.72 75.438,50.038 100,50.038 100,60 0,60 0,46.99 53.34,46.99 54.61,45.72
GND on Layer 1 "Top Layer-No Net" (solid, remove dead copper, pour order 16): 0,45.72 53.34,45.72 54.61,44.45 72.39,44.45 76.708,48.768 100,48.768 100,0 0,0
IGND on Layer 2 "Top Layer-No Net" (solid, remove dead copper, pour order 13): 71.12,45.72 75.438,50.038 100,50.038 100,60 0,60 0,46.99 53.34,46.99 54.61,45.72
GND on Layer 2 "Top Layer-No Net" (solid, remove dead copper, pour order 14): 0,45.72 53.34,45.72 54.61,44.45 72.39,44.45 76.708,48.768 100,48.768 100,0 0,0

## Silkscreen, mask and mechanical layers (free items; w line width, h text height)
Top Overlay:
  circle w0.254: c71.12,29.718 r0.1
  lines w0.22: 77.597,23.368 97.155,23.368
  lines w0.254: 70.358,31.242 70.358,32.512 ; 71.882,31.242 71.882,32.512
  text "Power +5V" at 14.732,44.958 h1.5
  text "100V" at 9.398,42.672 h1.5 r90
  text "80V" at 6.35,41.656 h1.5 r90
  text "60V" at 3.302,41.402 h1.5 r90
  text "Particle Physics DAQ Education Kit" at 77.597,23.622 h1.2
  text "EN" at 41.148,23.368 h1.5 r90
  text "Bias Voltage Supply" at 79.502,21.844 h0.9
Mechanical 1:
  lines w2.4: -1.2,12.4 -1.2,-1.2 12.4,-1.2 ; -1.2,16.7 -1.2,27.3 ; -1.2,32.3 -1.2,42.9 ; -1.2,47.6 -1.2,61.2 12.4,61.2 ; 17.1,-1.2 35.3,-1.2 ; 17.5,61.2 35.7,61.2 ; 40.8,-1.2 59,-1.2 ; 41,61.2 59.2,61.2 ; 64.3,-1.2 82.5,-1.2 ; 64.7,61.2 82.9,61.2 ; 87.6,-1.2 101.2,-1.2 101.2,12.4 ; 87.6,61.2 101.2,61.2 101.2,47.6 ; 101.2,17 101.2,27.6 ; 101.2,32.6 101.2,43.2 ; 12.4,61.2 12.4,61.2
